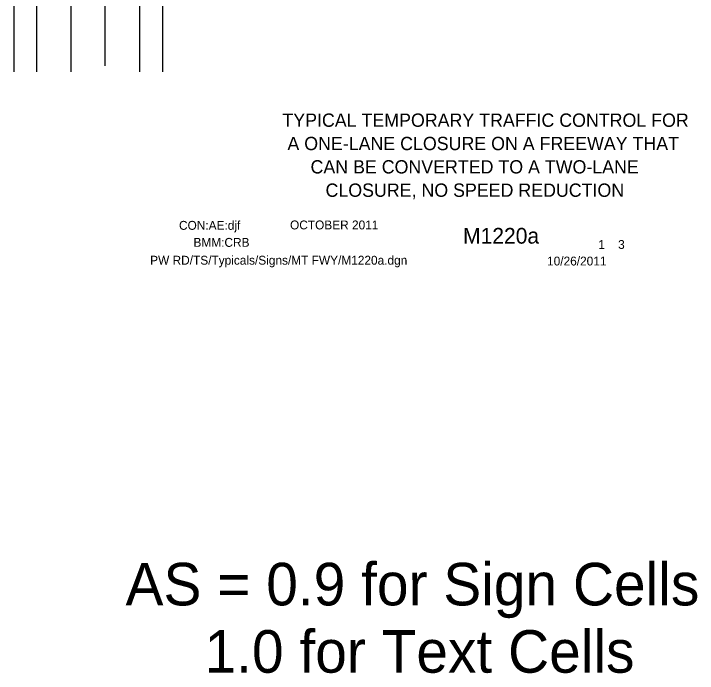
# Model space of a CAD drawing. Extents: x 16782 to 19504, y 6935 to 8243.
# Drawn here: x 16975.2 to 17452.9, y 6934.5 to 7395.3 of the extents above; entities that cross this region are included whole.
import ezdxf

# ---------------------------------------------------------------- set-up
doc = ezdxf.new("R2010")
doc.units = 0
for name, color, linetype in [('ALI_LEGAL_EX', 7, 'Continuous'), ('BORDER', 7, 'Continuous'), ('BORDER_SIGNAL_WO', 7, 'Continuous'), ('PAVT_EDGE_EX', 7, 'Continuous')]:
    doc.layers.add(name, color=color, linetype=linetype)

msp = doc.modelspace()

# ---------------------------------------------------------------- linework, layer by layer
at = {"layer": 'ALI_LEGAL_EX'}
for points in [[(17015.15, 7383.87), (17015.15, 7358.87)], [(17039.15, 7358.87), (17039.15, 7383.87)]]:
    msp.add_lwpolyline(points, dxfattribs=at)
at = {"layer": 'PAVT_EDGE_EX'}
for p, q in [((16975.15, 8208.67), (16975.15, 7354.69)), ((16991.15, 8208.67), (16991.15, 7354.69)), ((17063.15, 8208.67), (17063.15, 7354.69)), ((17079.15, 8208.67), (17079.15, 7354.69)), ((17015.15, 8183.87), (17015.15, 7354.69)), ((17039.15, 7358.87), (17039.15, 8183.87))]:
    msp.add_line(p, q, dxfattribs=at)

# ---------------------------------------------------------------- texts
at = {"layer": 'BORDER'}
for s, p in [('TYPICAL TEMPORARY TRAFFIC CONTROL FOR', (17162.96, 7316.24)), ('A ONE-LANE CLOSURE ON A FREEWAY THAT', (17166.47, 7299.94)), ('CAN BE CONVERTED TO A TWO-LANE ', (17182.62, 7283.64)), ('CLOSURE, NO SPEED REDUCTION ', (17193.1, 7267.34))]:
    msp.add_text(s, height=9.3, dxfattribs=at).set_placement(p)
at = {"layer": 'BORDER_SIGNAL_WO'}
for s, height, p in [('CON:AE:djf  ', 6.2, (17090.69, 7244.31)), ('    OCTOBER 2011    ', 6.2, (17159.08, 7244.59)), ('    M1220a   ', 11, (17272.86, 7234.63)), ('BMM:CRB   ', 6.2, (17100.81, 7232.42)), (' 1    3 ', 6.2, (17381.45, 7230.95)), ('PW RD/TS/Typicals/Signs/MT FWY/M1220a.dgn      ', 6.2, (17070.55, 7219.96)), ('10/26/2011    ', 6.2, (17347.93, 7219.38)), ('AS = 0.9 for Sign Cells', 29.7271, (17053.33, 6981.97)), ('     1.0 for Text Cells', 29.7271, (17053.33, 6934.96))]:
    msp.add_text(s, height=height, dxfattribs=at).set_placement(p)

doc.saveas('drawing.dxf')
